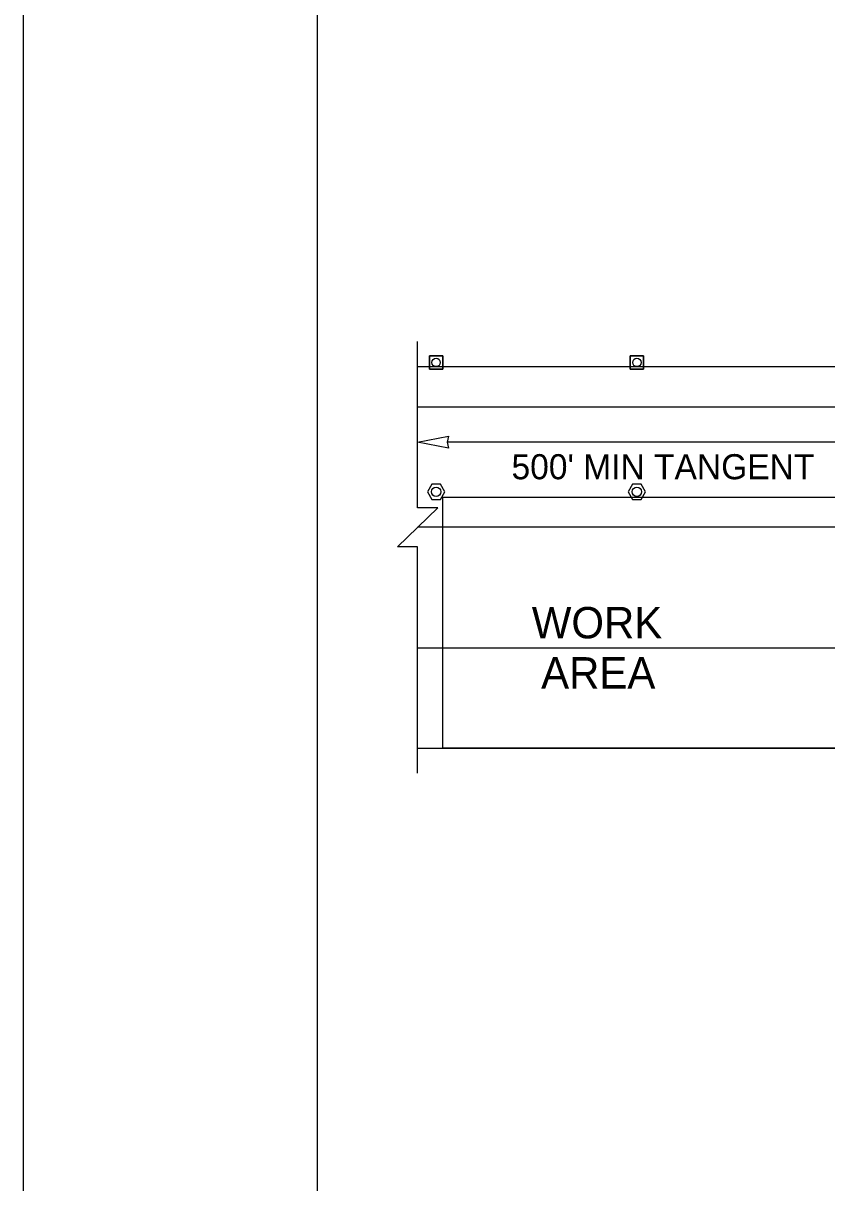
# Model space of a CAD drawing. Extents: x 99999 to 100116, y 99995 to 100013.
# Drawn here: x 100039.062 to 100041.625, y 100005.405 to 100009.102 of the extents above; entities that cross this region are included whole.
import ezdxf

# ---------------------------------------------------------------- set-up
doc = ezdxf.new("R2010")
doc.units = 0
for name, color, linetype in [('RD_MK_LineEdgeYellow', 7, 'Continuous'), ('RD_MK_LineLane', 7, 'Continuous'), ('SH_GI_PlotLimits', 7, 'Continuous'), ('SH_GI_SheetBorder', 7, 'Continuous'), ('TR_WZ_TallChanDevice', 7, 'Continuous'), ('TR_WZ_TrafficCone', 7, 'Continuous'), ('TR_WZ_WorkAreaLabel', 7, 'Continuous'), ('TR_WZ_WorkZoneDetails', 7, 'Continuous'), ('TR_WZ_WorkZoneTextCurrent', 7, 'Continuous')]:
    doc.layers.add(name, color=color, linetype=linetype)

msp = doc.modelspace()

# ---------------------------------------------------------------- linework, layer by layer
at = {"layer": 'RD_MK_LineEdgeYellow'}
for p, q in [((100040.32, 100007.8789), (100047.555, 100007.8789)), ((100040.32, 100007.1109), (100042.7119, 100007.1109))]:
    msp.add_line(p, q, dxfattribs=at)
at = {"layer": 'RD_MK_LineLane'}
msp.add_lwpolyline([(100047.555, 100007.4949), (100040.32, 100007.4949)], dxfattribs=at)
at = {"layer": 'SH_GI_PlotLimits'}
msp.add_lwpolyline([(100039.0625, 99999.6875), (100056.0625, 99999.6875), (100056.0625, 100010.6875), (100039.0625, 100010.6875)], close=True, dxfattribs=at)
at = {"layer": 'SH_GI_SheetBorder'}
msp.add_line((100040, 100010.375), (100040, 100000), dxfattribs=at)
at = {"layer": 'TR_WZ_TallChanDevice'}
for points in [[(100040.3928, 100007.6319), (100040.3651, 100007.6319), (100040.3512, 100007.6079), (100040.3651, 100007.5839), (100040.3928, 100007.5839), (100040.4066, 100007.6079)], [(100041.0328, 100007.6319), (100041.0051, 100007.6319), (100040.9912, 100007.6079), (100041.0051, 100007.5839), (100041.0328, 100007.5839), (100041.0466, 100007.6079)]]:
    msp.add_lwpolyline(points, close=True, dxfattribs=at)
for points in [[(100040.3928, 100007.6319), (100040.3651, 100007.6319), (100040.3512, 100007.6079), (100040.3651, 100007.5839), (100040.3928, 100007.5839), (100040.4066, 100007.6079), (100040.3928, 100007.6319)], [(100041.0328, 100007.6319), (100041.0051, 100007.6319), (100040.9912, 100007.6079), (100041.0051, 100007.5839), (100041.0328, 100007.5839), (100041.0466, 100007.6079), (100041.0328, 100007.6319)]]:
    msp.add_lwpolyline(points, dxfattribs=at)
for centre in [(100040.3789, 100007.6079), (100041.0189, 100007.6079)]:
    msp.add_circle(centre, 0.015, dxfattribs=at)
at = {"layer": 'TR_WZ_TrafficCone'}
for points in [[(100040.3576, 100008.0416), (100040.4003, 100008.0416), (100040.4003, 100007.9989), (100040.3576, 100007.9989), (100040.3576, 100008.0416)], [(100040.3576, 100007.9989), (100040.4003, 100007.9989), (100040.4003, 100008.0416), (100040.3576, 100008.0416), (100040.3576, 100007.9989)], [(100040.9976, 100008.0416), (100041.0403, 100008.0416), (100041.0403, 100007.9989), (100040.9976, 100007.9989), (100040.9976, 100008.0416)], [(100040.9976, 100007.9989), (100041.0403, 100007.9989), (100041.0403, 100008.0416), (100040.9976, 100008.0416), (100040.9976, 100007.9989)]]:
    msp.add_lwpolyline(points, dxfattribs=at)
for centre in [(100040.3789, 100008.0202), (100041.0189, 100008.0202)]:
    msp.add_circle(centre, 0.0133, dxfattribs=at)
at = {"layer": 'TR_WZ_WorkZoneDetails'}
for p, q in [((100040.32, 100008.0069), (100047.555, 100008.0069)), ((100040.32, 100008.0069), (100047.555, 100008.0069)), ((100041.8429, 100007.7659), (100040.4137, 100007.7659)), ((100040.32, 100006.7909), (100042.6438, 100006.7909))]:
    msp.add_line(p, q, dxfattribs=at)
msp.add_lwpolyline([(100040.32, 100006.7109), (100040.32, 100007.433), (100040.256, 100007.433), (100040.384, 100007.5569), (100040.32, 100007.5569), (100040.32, 100008.0869)], dxfattribs=at)
for points in [[(100040.32, 100007.7659), (100040.4183, 100007.7851), (100040.4137, 100007.7659), (100040.4183, 100007.7466)], [(100040.4, 100006.7909), (100040.4, 100007.5909), (100041.9366, 100007.5909), (100041.9366, 100006.7909)]]:
    msp.add_lwpolyline(points, close=True, dxfattribs=at)

# ---------------------------------------------------------------- texts
at = {"layer": 'TR_WZ_WorkAreaLabel'}
for s, p in [('WORK', (100040.684, 100007.1409)), ('AREA', (100040.7137, 100006.9809))]:
    msp.add_text(s, height=0.1, dxfattribs=at).set_placement(p)
at = {"layer": 'TR_WZ_WorkZoneTextCurrent'}
msp.add_text("500' MIN TANGENT", height=0.08, dxfattribs=at).set_placement((100040.6193, 100007.6479))

doc.saveas('drawing.dxf')
